(* Logix 5000 project; controller MyControlLogix vendor 1 type 14 code 51 rev 16.20; software revision 16.04; part 2 of 3 *)
(* tags used below, declared in another part *)
   AFC56 : AFC;
   AOI56AFC : AOI56AFC;
(* AOI56AFC, continued *)

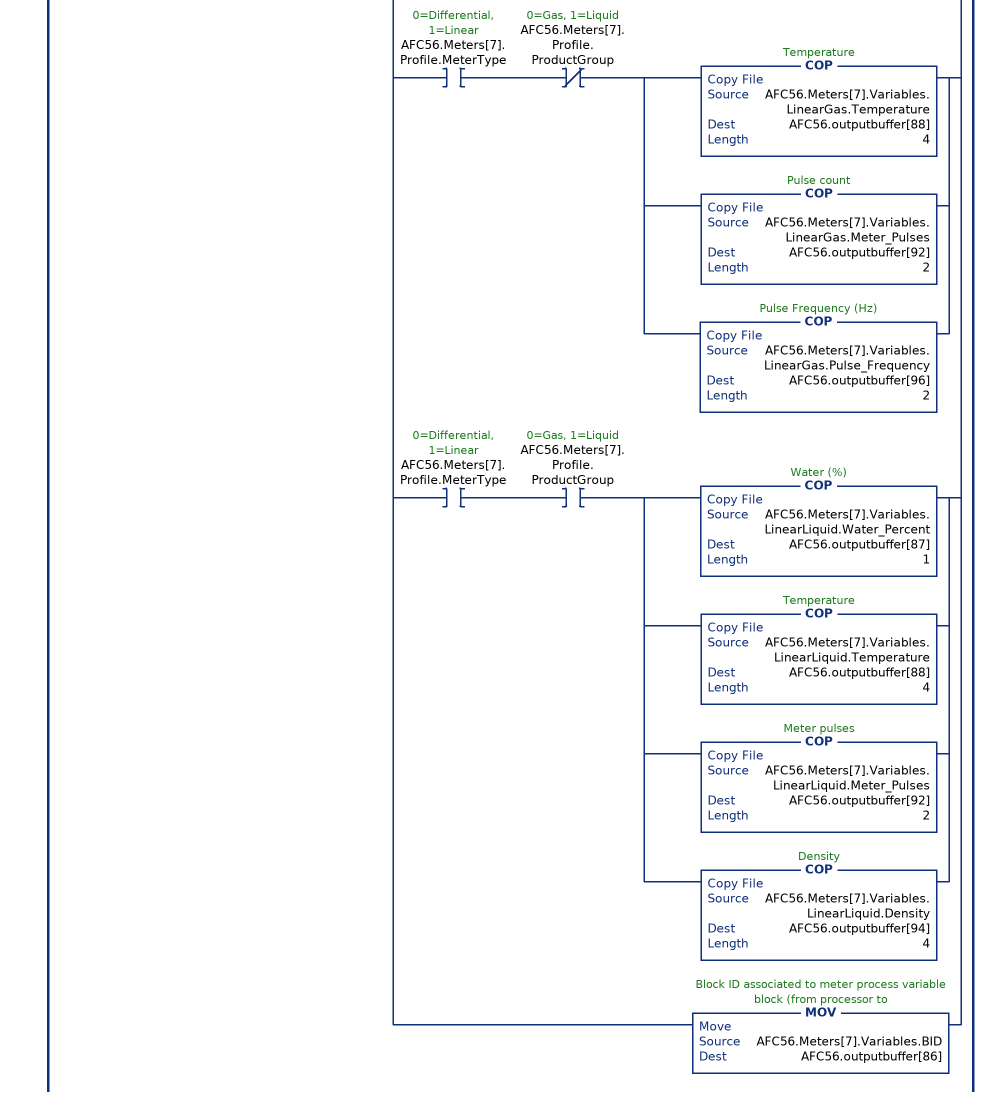
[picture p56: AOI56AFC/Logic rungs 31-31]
   31: XIO(AFC56.Flags.AFC_Set_Clock)LIM(1,AFC56.CycleCounter,16)[ADD(8,8192,AFC56.Meters[7].Variables.BID) ,XIO(AFC56.EnableStatus.Meter8) [OTE(AFC56.Meters[7].Variables.BID.8) ,OTU(AFC56.DisableMeter.Meter8) ] ,XIC(AFC56.EnableStatus.Meter8) OTU(AFC56.EnableMeter.Meter8) ,XIO(AFC56.Meters[7].Profile.MeterType) XIO(AFC56.Meters[7].Profile.ProductGroup) COP(AFC56.Meters[7].Variables.DifferentialGas.Temperature,AFC56.outputbuffer[88],6) ,XIO(AFC56.Meters[7].Profile.MeterType) XIC(AFC56.Meters[7].Profile.ProductGroup) [COP(AFC56.Meters[7].Variables.DifferentialLiquid.Water_Percent,AFC56.outputbuffer[87],1) ,COP(AFC56.Meters[7].Variables.DifferentialLiquid.Temperature,AFC56.outputbuffer[88],8) ] ,XIC(AFC56.Meters[7].Profile.MeterType) XIO(AFC56.Meters[7].Profile.ProductGroup) [COP(AFC56.Meters[7].Variables.LinearGas.Temperature,AFC56.outputbuffer[88],4) ,COP(AFC56.Meters[7].Variables.LinearGas.Meter_Pulses,AFC56.outputbuffer[92],2) ,COP(AFC56.Meters[7].Variables.LinearGas.Pulse_Frequency,AFC56.outputbuffer[96],2) ] ,XIC(AFC56.Meters[7].Profile.MeterType) XIC(AFC56.Meters[7].Profile.ProductGroup) [COP(AFC56.Meters[7].Variables.LinearLiquid.Water_Percent,AFC56.outputbuffer[87],1) ,COP(AFC56.Meters[7].Variables.LinearLiquid.Temperature,AFC56.outputbuffer[88],4) ,COP(AFC56.Meters[7].Variables.LinearLiquid.Meter_Pulses,AFC56.outputbuffer[92],2) ,COP(AFC56.Meters[7].Variables.LinearLiquid.Density,AFC56.outputbuffer[94],4) ] ,MOV(AFC56.Meters[7].Variables.BID,AFC56.outputbuffer[86]) ];
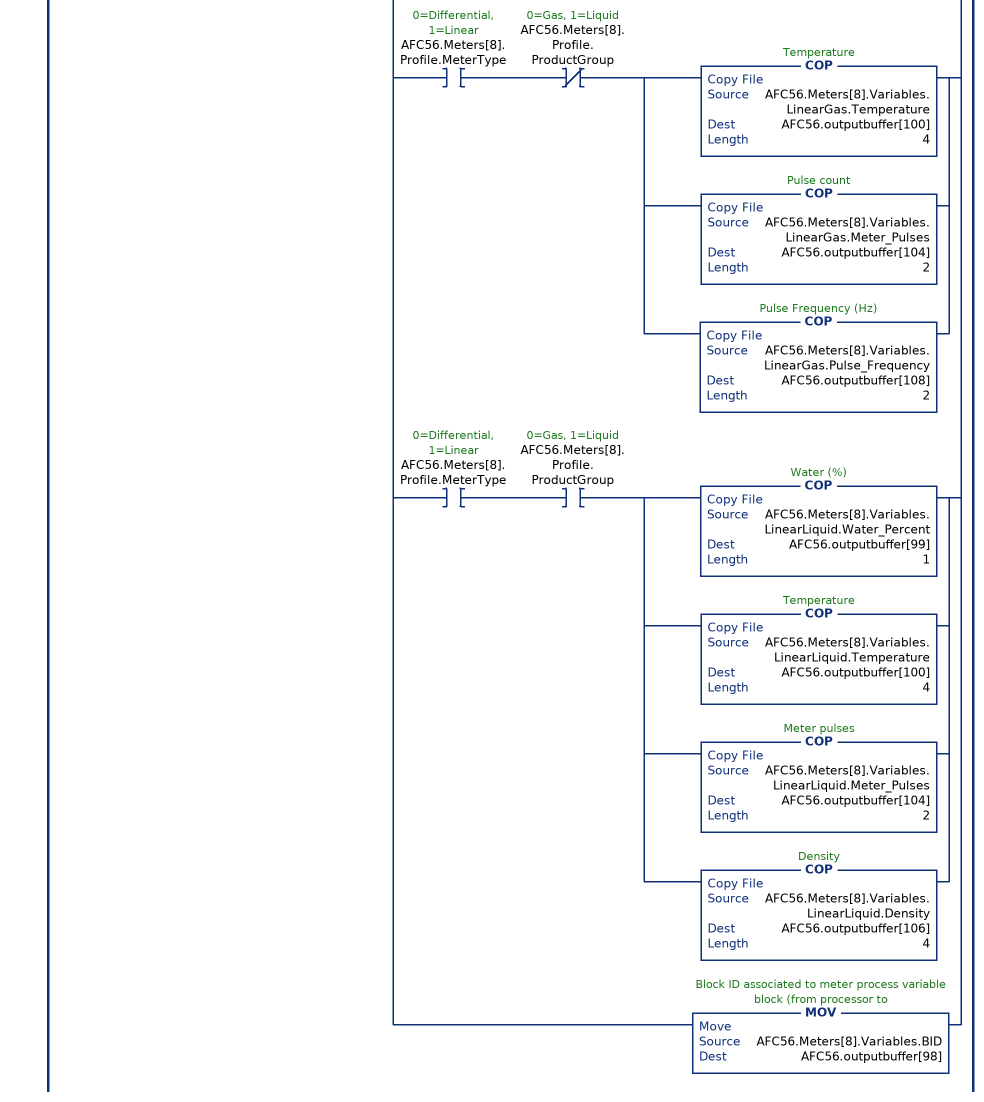
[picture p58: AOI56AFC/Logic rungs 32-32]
   32: XIO(AFC56.Flags.AFC_Set_Clock)LIM(1,AFC56.CycleCounter,16)[ADD(9,8192,AFC56.Meters[8].Variables.BID) ,XIO(AFC56.EnableStatus.Meter9) [OTE(AFC56.Meters[8].Variables.BID.8) ,OTU(AFC56.DisableMeter.Meter9) ] ,XIC(AFC56.EnableStatus.Meter9) OTU(AFC56.EnableMeter.Meter9) ,XIO(AFC56.Meters[8].Profile.MeterType) XIO(AFC56.Meters[8].Profile.ProductGroup) COP(AFC56.Meters[8].Variables.DifferentialGas.Temperature,AFC56.outputbuffer[100],6) ,XIO(AFC56.Meters[8].Profile.MeterType) XIC(AFC56.Meters[8].Profile.ProductGroup) [COP(AFC56.Meters[8].Variables.DifferentialLiquid.Water_Percent,AFC56.outputbuffer[99],1) ,COP(AFC56.Meters[8].Variables.DifferentialLiquid.Temperature,AFC56.outputbuffer[100],8) ] ,XIC(AFC56.Meters[8].Profile.MeterType) XIO(AFC56.Meters[8].Profile.ProductGroup) [COP(AFC56.Meters[8].Variables.LinearGas.Temperature,AFC56.outputbuffer[100],4) ,COP(AFC56.Meters[8].Variables.LinearGas.Meter_Pulses,AFC56.outputbuffer[104],2) ,COP(AFC56.Meters[8].Variables.LinearGas.Pulse_Frequency,AFC56.outputbuffer[108],2) ] ,XIC(AFC56.Meters[8].Profile.MeterType) XIC(AFC56.Meters[8].Profile.ProductGroup) [COP(AFC56.Meters[8].Variables.LinearLiquid.Water_Percent,AFC56.outputbuffer[99],1) ,COP(AFC56.Meters[8].Variables.LinearLiquid.Temperature,AFC56.outputbuffer[100],4) ,COP(AFC56.Meters[8].Variables.LinearLiquid.Meter_Pulses,AFC56.outputbuffer[104],2) ,COP(AFC56.Meters[8].Variables.LinearLiquid.Density,AFC56.outputbuffer[106],4) ] ,MOV(AFC56.Meters[8].Variables.BID,AFC56.outputbuffer[98]) ];
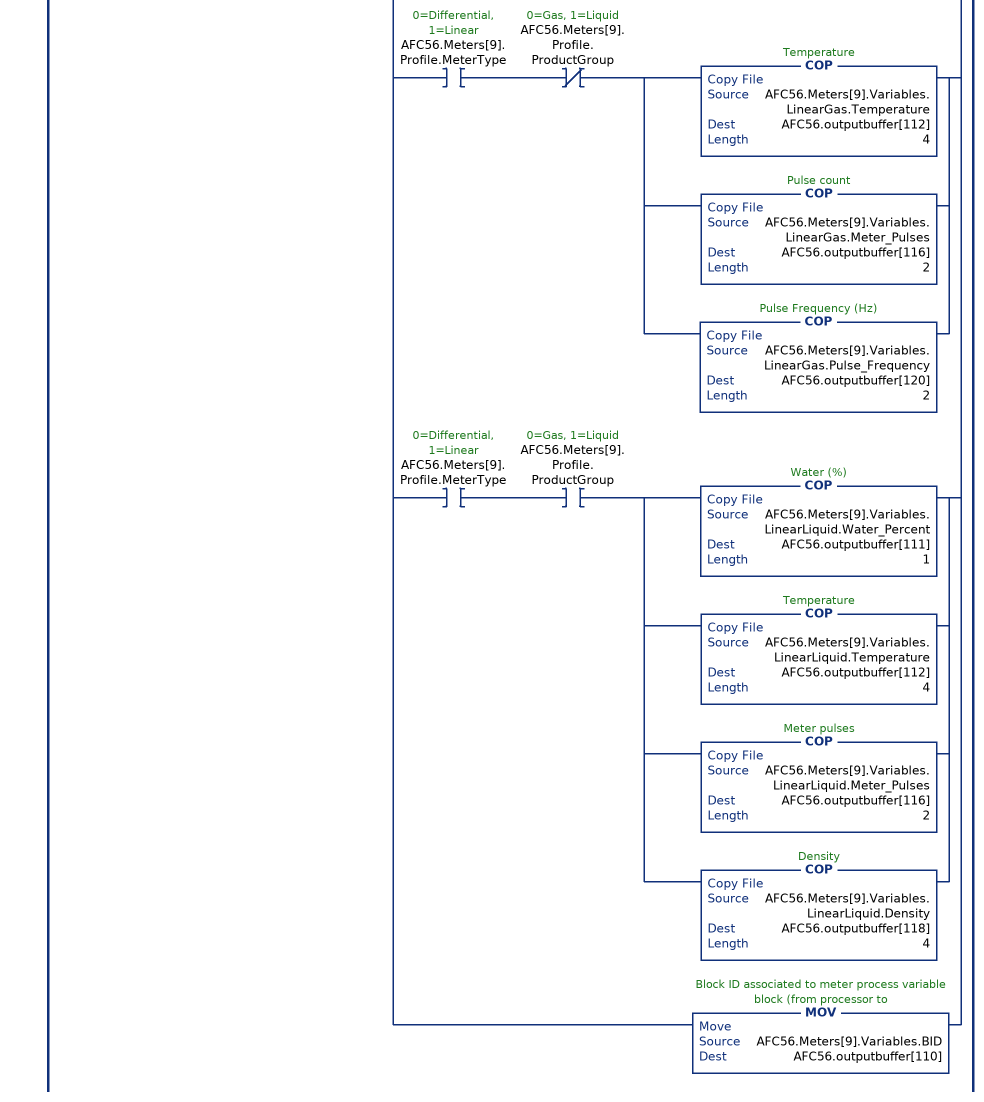
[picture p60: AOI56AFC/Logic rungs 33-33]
   33: XIO(AFC56.Flags.AFC_Set_Clock)LIM(1,AFC56.CycleCounter,16)[ADD(10,8192,AFC56.Meters[9].Variables.BID) ,XIO(AFC56.EnableStatus.Meter10) [OTE(AFC56.Meters[9].Variables.BID.8) ,OTU(AFC56.DisableMeter.Meter10) ] ,XIC(AFC56.EnableStatus.Meter10) OTU(AFC56.EnableMeter.Meter10) ,XIO(AFC56.Meters[9].Profile.MeterType) XIO(AFC56.Meters[9].Profile.ProductGroup) COP(AFC56.Meters[9].Variables.DifferentialGas.Temperature,AFC56.outputbuffer[112],6) ,XIO(AFC56.Meters[9].Profile.MeterType) XIC(AFC56.Meters[9].Profile.ProductGroup) [COP(AFC56.Meters[9].Variables.DifferentialLiquid.Water_Percent,AFC56.outputbuffer[111],1) ,COP(AFC56.Meters[9].Variables.DifferentialLiquid.Temperature,AFC56.outputbuffer[112],8) ] ,XIC(AFC56.Meters[9].Profile.MeterType) XIO(AFC56.Meters[9].Profile.ProductGroup) [COP(AFC56.Meters[9].Variables.LinearGas.Temperature,AFC56.outputbuffer[112],4) ,COP(AFC56.Meters[9].Variables.LinearGas.Meter_Pulses,AFC56.outputbuffer[116],2) ,COP(AFC56.Meters[9].Variables.LinearGas.Pulse_Frequency,AFC56.outputbuffer[120],2) ] ,XIC(AFC56.Meters[9].Profile.MeterType) XIC(AFC56.Meters[9].Profile.ProductGroup) [COP(AFC56.Meters[9].Variables.LinearLiquid.Water_Percent,AFC56.outputbuffer[111],1) ,COP(AFC56.Meters[9].Variables.LinearLiquid.Temperature,AFC56.outputbuffer[112],4) ,COP(AFC56.Meters[9].Variables.LinearLiquid.Meter_Pulses,AFC56.outputbuffer[116],2) ,COP(AFC56.Meters[9].Variables.LinearLiquid.Density,AFC56.outputbuffer[118],4) ] ,MOV(AFC56.Meters[9].Variables.BID,AFC56.outputbuffer[110]) ];
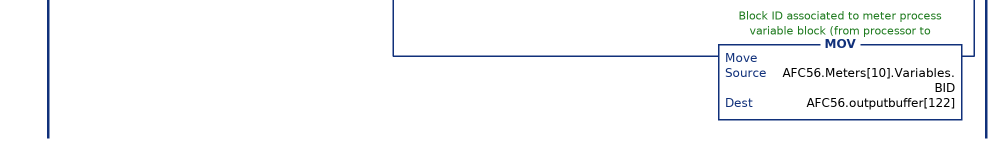
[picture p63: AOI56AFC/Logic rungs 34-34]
   34: XIO(AFC56.Flags.AFC_Set_Clock)LIM(1,AFC56.CycleCounter,16)[ADD(11,8192,AFC56.Meters[10].Variables.BID) ,XIO(AFC56.EnableStatus.Meter11) [OTE(AFC56.Meters[10].Variables.BID.8) ,OTU(AFC56.DisableMeter.Meter11) ] ,XIC(AFC56.EnableStatus.Meter11) OTU(AFC56.EnableMeter.Meter11) ,XIO(AFC56.Meters[10].Profile.MeterType) XIO(AFC56.Meters[10].Profile.ProductGroup) COP(AFC56.Meters[10].Variables.DifferentialGas.Temperature,AFC56.outputbuffer[124],6) ,XIO(AFC56.Meters[10].Profile.MeterType) XIC(AFC56.Meters[10].Profile.ProductGroup) [COP(AFC56.Meters[10].Variables.DifferentialLiquid.Water_Percent,AFC56.outputbuffer[123],1) ,COP(AFC56.Meters[10].Variables.DifferentialLiquid.Temperature,AFC56.outputbuffer[124],8) ] ,XIC(AFC56.Meters[10].Profile.MeterType) XIO(AFC56.Meters[10].Profile.ProductGroup) [COP(AFC56.Meters[10].Variables.LinearGas.Temperature,AFC56.outputbuffer[124],4) ,COP(AFC56.Meters[10].Variables.LinearGas.Meter_Pulses,AFC56.outputbuffer[128],2) ,COP(AFC56.Meters[10].Variables.LinearGas.Pulse_Frequency,AFC56.outputbuffer[132],2) ] ,XIC(AFC56.Meters[10].Profile.MeterType) XIC(AFC56.Meters[10].Profile.ProductGroup) [COP(AFC56.Meters[10].Variables.LinearLiquid.Water_Percent,AFC56.outputbuffer[123],1) ,COP(AFC56.Meters[10].Variables.LinearLiquid.Temperature,AFC56.outputbuffer[124],4) ,COP(AFC56.Meters[10].Variables.LinearLiquid.Meter_Pulses,AFC56.outputbuffer[128],2) ,COP(AFC56.Meters[10].Variables.LinearLiquid.Density,AFC56.outputbuffer[130],4) ] ,MOV(AFC56.Meters[10].Variables.BID,AFC56.outputbuffer[122]) ];
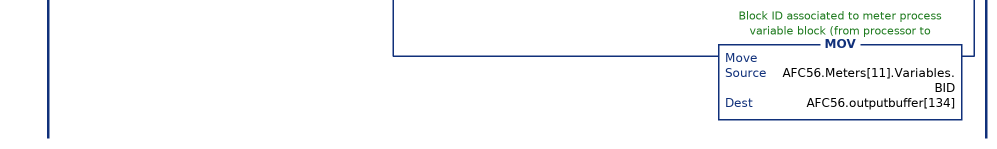
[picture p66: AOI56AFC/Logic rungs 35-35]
   35: XIO(AFC56.Flags.AFC_Set_Clock)LIM(1,AFC56.CycleCounter,16)[ADD(12,8192,AFC56.Meters[11].Variables.BID) ,XIO(AFC56.EnableStatus.Meter12) [OTE(AFC56.Meters[11].Variables.BID.8) ,OTU(AFC56.DisableMeter.Meter12) ] ,XIC(AFC56.EnableStatus.Meter12) OTU(AFC56.EnableMeter.Meter12) ,XIO(AFC56.Meters[11].Profile.MeterType) XIO(AFC56.Meters[11].Profile.ProductGroup) COP(AFC56.Meters[11].Variables.DifferentialGas.Temperature,AFC56.outputbuffer[136],6) ,XIO(AFC56.Meters[11].Profile.MeterType) XIC(AFC56.Meters[11].Profile.ProductGroup) [COP(AFC56.Meters[11].Variables.DifferentialLiquid.Water_Percent,AFC56.outputbuffer[135],1) ,COP(AFC56.Meters[11].Variables.DifferentialLiquid.Temperature,AFC56.outputbuffer[136],8) ] ,XIC(AFC56.Meters[11].Profile.MeterType) XIO(AFC56.Meters[11].Profile.ProductGroup) [COP(AFC56.Meters[11].Variables.LinearGas.Temperature,AFC56.outputbuffer[136],4) ,COP(AFC56.Meters[11].Variables.LinearGas.Meter_Pulses,AFC56.outputbuffer[140],2) ,COP(AFC56.Meters[11].Variables.LinearGas.Pulse_Frequency,AFC56.outputbuffer[144],2) ] ,XIC(AFC56.Meters[11].Profile.MeterType) XIC(AFC56.Meters[11].Profile.ProductGroup) [COP(AFC56.Meters[11].Variables.LinearLiquid.Water_Percent,AFC56.outputbuffer[135],1) ,COP(AFC56.Meters[11].Variables.LinearLiquid.Temperature,AFC56.outputbuffer[136],4) ,COP(AFC56.Meters[11].Variables.LinearLiquid.Meter_Pulses,AFC56.outputbuffer[140],2) ,COP(AFC56.Meters[11].Variables.LinearLiquid.Density,AFC56.outputbuffer[142],4) ] ,MOV(AFC56.Meters[11].Variables.BID,AFC56.outputbuffer[134]) ];
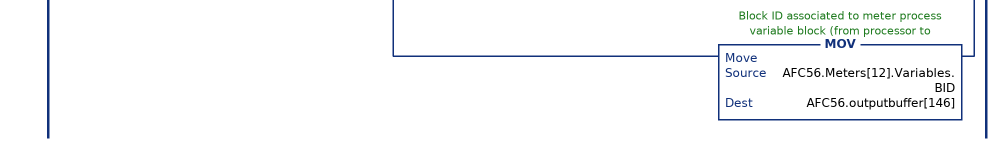
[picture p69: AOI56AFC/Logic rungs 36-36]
   36: XIO(AFC56.Flags.AFC_Set_Clock)LIM(1,AFC56.CycleCounter,16)[ADD(13,8192,AFC56.Meters[12].Variables.BID) ,XIO(AFC56.EnableStatus.Meter13) [OTE(AFC56.Meters[12].Variables.BID.8) ,OTU(AFC56.DisableMeter.Meter13) ] ,XIC(AFC56.EnableStatus.Meter13) OTU(AFC56.EnableMeter.Meter13) ,XIO(AFC56.Meters[12].Profile.MeterType) XIO(AFC56.Meters[12].Profile.ProductGroup) COP(AFC56.Meters[12].Variables.DifferentialGas.Temperature,AFC56.outputbuffer[148],6) ,XIO(AFC56.Meters[12].Profile.MeterType) XIC(AFC56.Meters[12].Profile.ProductGroup) [COP(AFC56.Meters[12].Variables.DifferentialLiquid.Water_Percent,AFC56.outputbuffer[147],1) ,COP(AFC56.Meters[12].Variables.DifferentialLiquid.Temperature,AFC56.outputbuffer[148],8) ] ,XIC(AFC56.Meters[12].Profile.MeterType) XIO(AFC56.Meters[12].Profile.ProductGroup) [COP(AFC56.Meters[12].Variables.LinearGas.Temperature,AFC56.outputbuffer[148],4) ,COP(AFC56.Meters[12].Variables.LinearGas.Meter_Pulses,AFC56.outputbuffer[152],2) ,COP(AFC56.Meters[12].Variables.LinearGas.Pulse_Frequency,AFC56.outputbuffer[156],2) ] ,XIC(AFC56.Meters[12].Profile.MeterType) XIC(AFC56.Meters[12].Profile.ProductGroup) [COP(AFC56.Meters[12].Variables.LinearLiquid.Water_Percent,AFC56.outputbuffer[147],1) ,COP(AFC56.Meters[12].Variables.LinearLiquid.Temperature,AFC56.outputbuffer[148],4) ,COP(AFC56.Meters[12].Variables.LinearLiquid.Meter_Pulses,AFC56.outputbuffer[152],2) ,COP(AFC56.Meters[12].Variables.LinearLiquid.Density,AFC56.outputbuffer[154],4) ] ,MOV(AFC56.Meters[12].Variables.BID,AFC56.outputbuffer[146]) ];
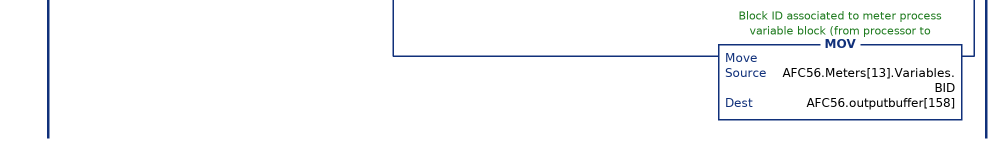
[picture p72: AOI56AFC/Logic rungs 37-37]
   37: XIO(AFC56.Flags.AFC_Set_Clock)LIM(1,AFC56.CycleCounter,16)[ADD(14,8192,AFC56.Meters[13].Variables.BID) ,XIO(AFC56.EnableStatus.Meter14) [OTE(AFC56.Meters[13].Variables.BID.8) ,OTU(AFC56.DisableMeter.Meter14) ] ,XIC(AFC56.EnableStatus.Meter14) OTU(AFC56.EnableMeter.Meter14) ,XIO(AFC56.Meters[13].Profile.MeterType) XIO(AFC56.Meters[13].Profile.ProductGroup) COP(AFC56.Meters[13].Variables.DifferentialGas.Temperature,AFC56.outputbuffer[160],6) ,XIO(AFC56.Meters[13].Profile.MeterType) XIC(AFC56.Meters[13].Profile.ProductGroup) [COP(AFC56.Meters[13].Variables.DifferentialLiquid.Water_Percent,AFC56.outputbuffer[159],1) ,COP(AFC56.Meters[13].Variables.DifferentialLiquid.Temperature,AFC56.outputbuffer[160],8) ] ,XIC(AFC56.Meters[13].Profile.MeterType) XIO(AFC56.Meters[13].Profile.ProductGroup) [COP(AFC56.Meters[13].Variables.LinearGas.Temperature,AFC56.outputbuffer[160],4) ,COP(AFC56.Meters[13].Variables.LinearGas.Meter_Pulses,AFC56.outputbuffer[164],2) ,COP(AFC56.Meters[13].Variables.LinearGas.Pulse_Frequency,AFC56.outputbuffer[168],2) ] ,XIC(AFC56.Meters[13].Profile.MeterType) XIC(AFC56.Meters[13].Profile.ProductGroup) [COP(AFC56.Meters[13].Variables.LinearLiquid.Water_Percent,AFC56.outputbuffer[159],1) ,COP(AFC56.Meters[13].Variables.LinearLiquid.Temperature,AFC56.outputbuffer[160],4) ,COP(AFC56.Meters[13].Variables.LinearLiquid.Meter_Pulses,AFC56.outputbuffer[164],2) ,COP(AFC56.Meters[13].Variables.LinearLiquid.Density,AFC56.outputbuffer[166],4) ] ,MOV(AFC56.Meters[13].Variables.BID,AFC56.outputbuffer[158]) ];
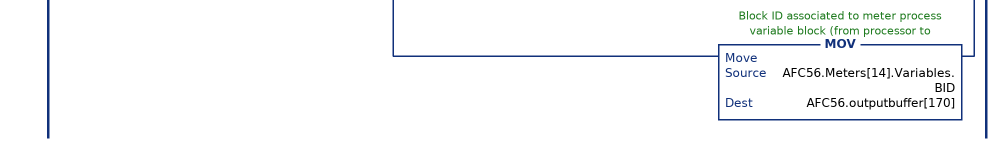
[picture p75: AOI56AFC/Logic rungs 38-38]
   38: XIO(AFC56.Flags.AFC_Set_Clock)LIM(1,AFC56.CycleCounter,16)[ADD(15,8192,AFC56.Meters[14].Variables.BID) ,XIO(AFC56.EnableStatus.Meter15) [OTE(AFC56.Meters[14].Variables.BID.8) ,OTU(AFC56.DisableMeter.Meter15) ] ,XIC(AFC56.EnableStatus.Meter15) OTU(AFC56.EnableMeter.Meter15) ,XIO(AFC56.Meters[14].Profile.MeterType) XIO(AFC56.Meters[14].Profile.ProductGroup) COP(AFC56.Meters[14].Variables.DifferentialGas.Temperature,AFC56.outputbuffer[172],6) ,XIO(AFC56.Meters[14].Profile.MeterType) XIC(AFC56.Meters[14].Profile.ProductGroup) [COP(AFC56.Meters[14].Variables.DifferentialLiquid.Water_Percent,AFC56.outputbuffer[171],1) ,COP(AFC56.Meters[14].Variables.DifferentialLiquid.Temperature,AFC56.outputbuffer[172],8) ] ,XIC(AFC56.Meters[14].Profile.MeterType) XIO(AFC56.Meters[14].Profile.ProductGroup) [COP(AFC56.Meters[14].Variables.LinearGas.Temperature,AFC56.outputbuffer[172],4) ,COP(AFC56.Meters[14].Variables.LinearGas.Meter_Pulses,AFC56.outputbuffer[176],2) ,COP(AFC56.Meters[14].Variables.LinearGas.Pulse_Frequency,AFC56.outputbuffer[180],2) ] ,XIC(AFC56.Meters[14].Profile.MeterType) XIC(AFC56.Meters[14].Profile.ProductGroup) [COP(AFC56.Meters[14].Variables.LinearLiquid.Water_Percent,AFC56.outputbuffer[171],1) ,COP(AFC56.Meters[14].Variables.LinearLiquid.Temperature,AFC56.outputbuffer[172],4) ,COP(AFC56.Meters[14].Variables.LinearLiquid.Meter_Pulses,AFC56.outputbuffer[176],2) ,COP(AFC56.Meters[14].Variables.LinearLiquid.Density,AFC56.outputbuffer[178],4) ] ,MOV(AFC56.Meters[14].Variables.BID,AFC56.outputbuffer[170]) ];
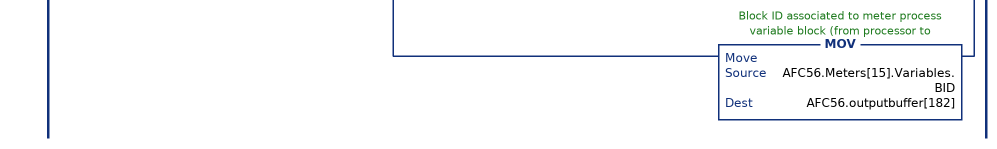
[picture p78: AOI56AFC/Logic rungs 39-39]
   39: XIO(AFC56.Flags.AFC_Set_Clock)LIM(1,AFC56.CycleCounter,16)[ADD(16,8192,AFC56.Meters[15].Variables.BID) ,XIO(AFC56.EnableStatus.Meter16) [OTE(AFC56.Meters[15].Variables.BID.8) ,OTU(AFC56.DisableMeter.Meter16) ] ,XIC(AFC56.EnableStatus.Meter16) OTU(AFC56.EnableMeter.Meter16) ,XIO(AFC56.Meters[15].Profile.MeterType) XIO(AFC56.Meters[15].Profile.ProductGroup) COP(AFC56.Meters[15].Variables.DifferentialGas.Temperature,AFC56.outputbuffer[184],6) ,XIO(AFC56.Meters[15].Profile.MeterType) XIC(AFC56.Meters[15].Profile.ProductGroup) [COP(AFC56.Meters[15].Variables.DifferentialLiquid.Water_Percent,AFC56.outputbuffer[183],1) ,COP(AFC56.Meters[15].Variables.DifferentialLiquid.Temperature,AFC56.outputbuffer[184],8) ] ,XIC(AFC56.Meters[15].Profile.MeterType) XIO(AFC56.Meters[15].Profile.ProductGroup) [COP(AFC56.Meters[15].Variables.LinearGas.Temperature,AFC56.outputbuffer[184],4) ,COP(AFC56.Meters[15].Variables.LinearGas.Meter_Pulses,AFC56.outputbuffer[188],2) ,COP(AFC56.Meters[15].Variables.LinearGas.Pulse_Frequency,AFC56.outputbuffer[192],2) ] ,XIC(AFC56.Meters[15].Profile.MeterType) XIC(AFC56.Meters[15].Profile.ProductGroup) [COP(AFC56.Meters[15].Variables.LinearLiquid.Water_Percent,AFC56.outputbuffer[183],1) ,COP(AFC56.Meters[15].Variables.LinearLiquid.Temperature,AFC56.outputbuffer[184],4) ,COP(AFC56.Meters[15].Variables.LinearLiquid.Meter_Pulses,AFC56.outputbuffer[188],2) ,COP(AFC56.Meters[15].Variables.LinearLiquid.Density,AFC56.outputbuffer[190],4) ] ,MOV(AFC56.Meters[15].Variables.BID,AFC56.outputbuffer[182]) ];
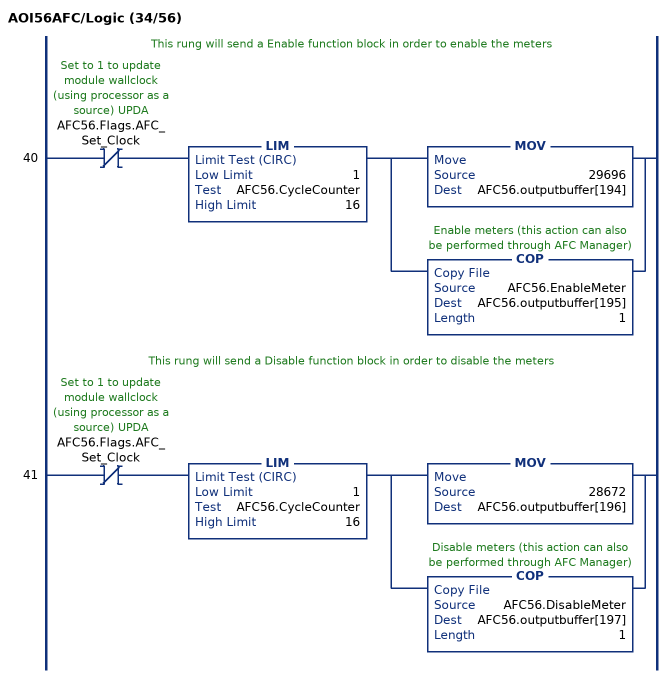
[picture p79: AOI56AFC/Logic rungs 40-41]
   // This rung will send a Enable function block in order to enable the meters
   40: XIO(AFC56.Flags.AFC_Set_Clock)LIM(1,AFC56.CycleCounter,16)[MOV(29696,AFC56.outputbuffer[194]) ,COP(AFC56.EnableMeter,AFC56.outputbuffer[195],1) ];
   // This rung will send a Disable function block in order to disable the meters
   41: XIO(AFC56.Flags.AFC_Set_Clock)LIM(1,AFC56.CycleCounter,16)[MOV(28672,AFC56.outputbuffer[196]) ,COP(AFC56.DisableMeter,AFC56.outputbuffer[197],1) ];
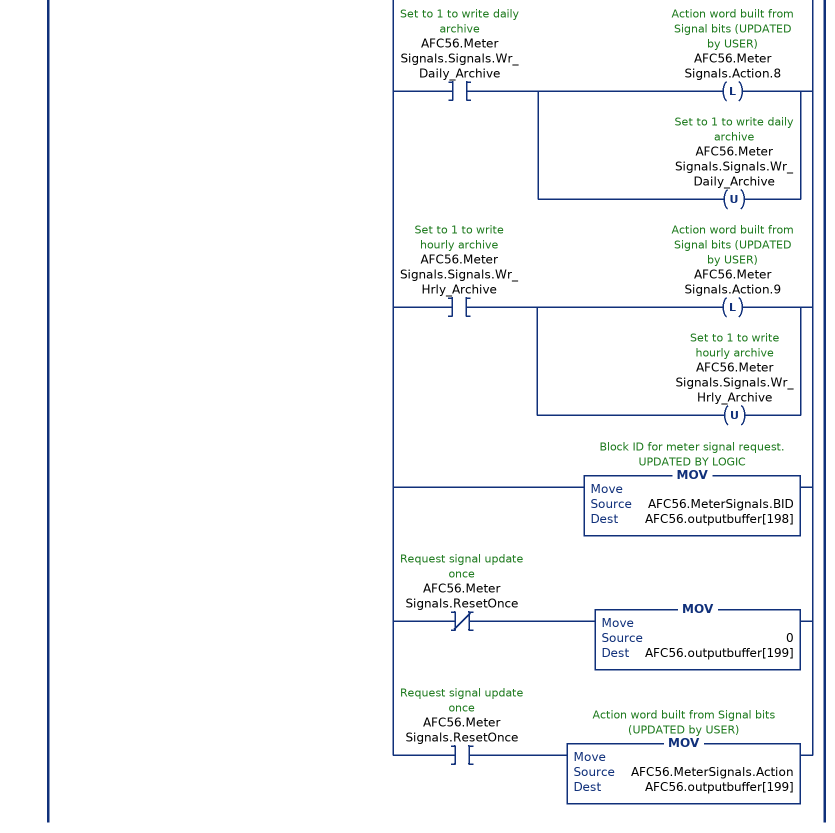
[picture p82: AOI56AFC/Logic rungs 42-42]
   // This rung will allow the ladder logic to reset any accumulator or to write a daily or hourly archive
   42: XIO(AFC56.Flags.AFC_Set_Clock)LIM(1,AFC56.CycleCounter,16)[ADD(12288,AFC56.MeterSignals.Meter,AFC56.MeterSignals.BID) ,XIO(AFC56.MeterSignals.Enable) OTE(AFC56.MeterSignals.BID.8) ,XIC(AFC56.MeterSignals.Signals.Sel_Stream1) [OTL(AFC56.MeterSignals.Action.0) ,OTU(AFC56.MeterSignals.Signals.Sel_Stream1) ] ,XIC(AFC56.MeterSignals.Signals.Sel_Stream2) [OTL(AFC56.MeterSignals.Action.1) ,OTU(AFC56.MeterSignals.Signals.Sel_Stream2) ] ,XIC(AFC56.MeterSignals.Signals.Sel_Stream3) [OTL(AFC56.MeterSignals.Action.2) ,OTU(AFC56.MeterSignals.Signals.Sel_Stream3) ] ,XIC(AFC56.MeterSignals.Signals.Sel_Stream4) [OTL(AFC56.MeterSignals.Action.3) ,OTU(AFC56.MeterSignals.Signals.Sel_Stream4) ] ,XIC(AFC56.MeterSignals.Signals.Res_Acc1) [OTL(AFC56.MeterSignals.Action.4) ,OTU(AFC56.MeterSignals.Signals.Res_Acc1) ] ,XIC(AFC56.MeterSignals.Signals.Res_Acc2) [OTL(AFC56.MeterSignals.Action.5) ,OTU(AFC56.MeterSignals.Signals.Res_Acc2) ] ,XIC(AFC56.MeterSignals.Signals.Res_Acc3) [OTL(AFC56.MeterSignals.Action.6) ,OTU(AFC56.MeterSignals.Signals.Res_Acc3) ] ,XIC(AFC56.MeterSignals.Signals.Res_Acc4) [OTL(AFC56.MeterSignals.Action.7) ,OTU(AFC56.MeterSignals.Signals.Res_Acc4) ] ,XIC(AFC56.MeterSignals.Signals.Wr_Daily_Archive) [OTL(AFC56.MeterSignals.Action.8) ,OTU(AFC56.MeterSignals.Signals.Wr_Daily_Archive) ] ,XIC(AFC56.MeterSignals.Signals.Wr_Hrly_Archive) [OTL(AFC56.MeterSignals.Action.9) ,OTU(AFC56.MeterSignals.Signals.Wr_Hrly_Archive) ] ,MOV(AFC56.MeterSignals.BID,AFC56.outputbuffer[198]) ,XIO(AFC56.MeterSignals.ResetOnce) MOV(0,AFC56.outputbuffer[199]) ,XIC(AFC56.MeterSignals.ResetOnce) MOV(AFC56.MeterSignals.Action,AFC56.outputbuffer[199]) ];
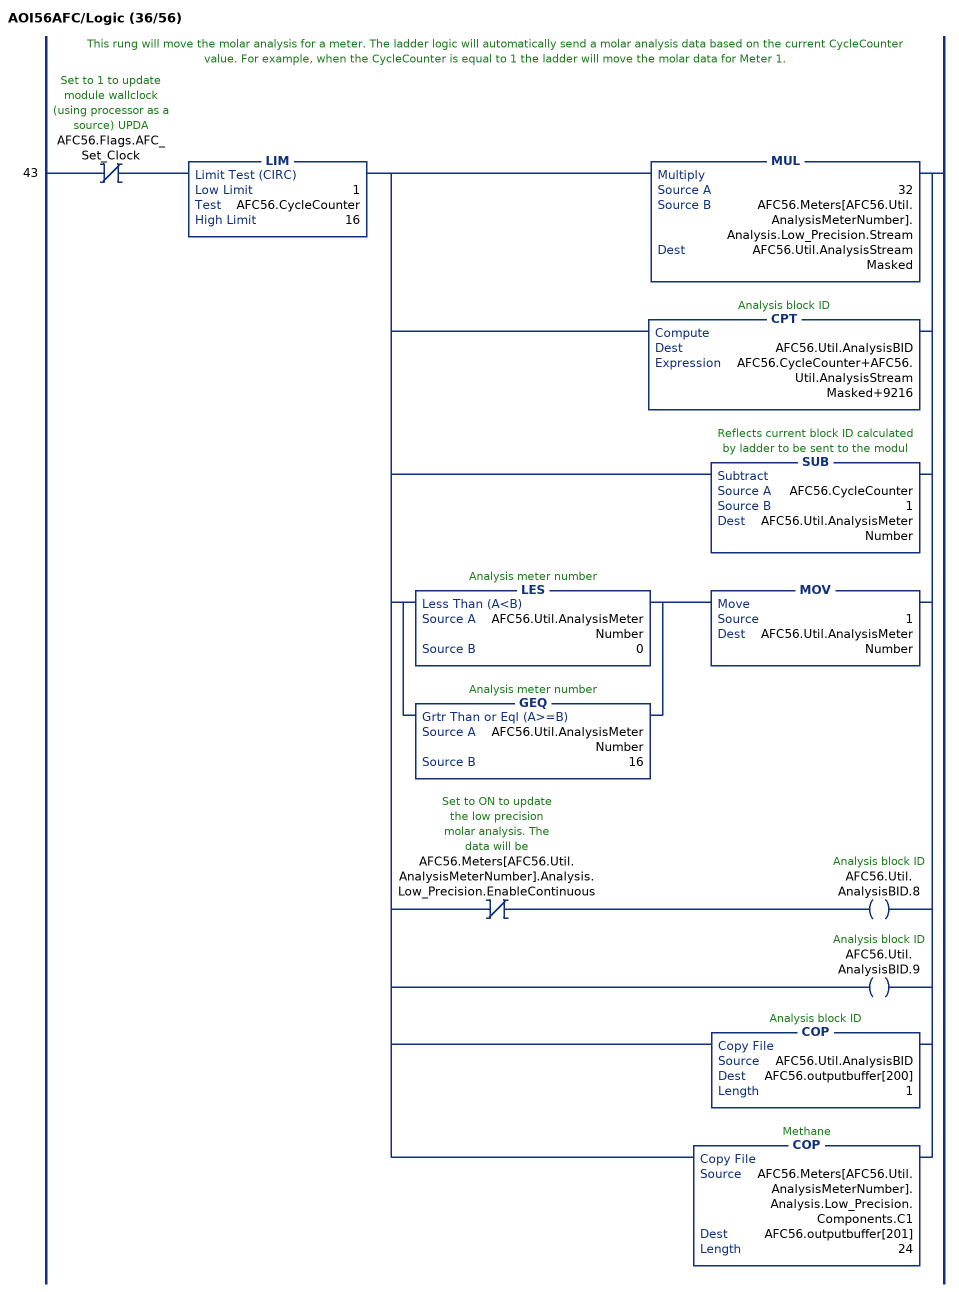
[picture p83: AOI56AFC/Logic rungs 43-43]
   // This rung will move the molar analysis for a meter. The ladder logic will automatically send a molar analysis data based on the current CycleCounter value. For example, when the CycleCounter is equal to 1 the ladder will move the molar data for Meter 1.
   43: XIO(AFC56.Flags.AFC_Set_Clock)LIM(1,AFC56.CycleCounter,16)[MUL(32,AFC56.Meters[AFC56.Util.AnalysisMeterNumber].Analysis.Low_Precision.Stream,AFC56.Util.AnalysisStreamMasked) ,CPT(AFC56.Util.AnalysisBID,AFC56.CycleCounter+AFC56.Util.AnalysisStreamMasked+9216) ,SUB(AFC56.CycleCounter,1,AFC56.Util.AnalysisMeterNumber) ,[LES(AFC56.Util.AnalysisMeterNumber,0) ,GEQ(AFC56.Util.AnalysisMeterNumber,16) ] MOV(1,AFC56.Util.AnalysisMeterNumber) ,XIO(AFC56.Meters[AFC56.Util.AnalysisMeterNumber].Analysis.Low_Precision.EnableContinuous) OTE(AFC56.Util.AnalysisBID.8) ,OTE(AFC56.Util.AnalysisBID.9) ,COP(AFC56.Util.AnalysisBID,AFC56.outputbuffer[200],1) ,COP(AFC56.Meters[AFC56.Util.AnalysisMeterNumber].Analysis.Low_Precision.Components.C1,AFC56.outputbuffer[201],24) ];
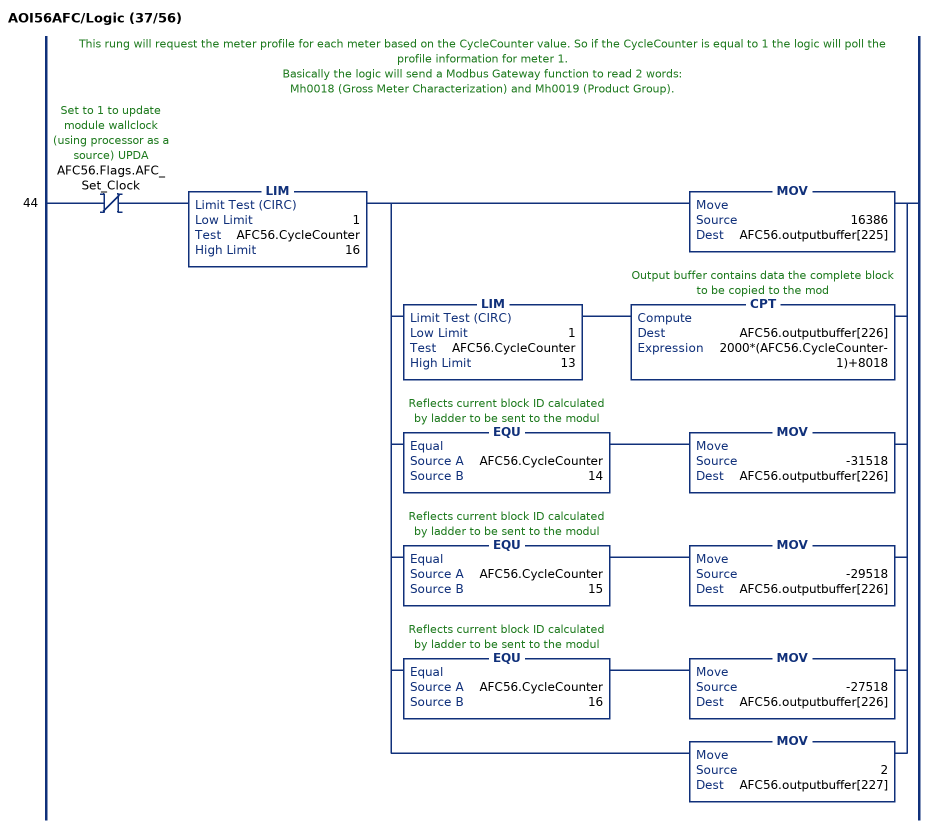
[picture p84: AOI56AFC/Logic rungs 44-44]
   // This rung will request the meter profile for each meter based on the CycleCounter value. So if the CycleCounter is equal to 1 the logic will poll the profile information for meter 1.
   // Basically the logic will send a Modbus Gateway function to read 2 words:
   // Mh0018 (Gross Meter Characterization) and Mh0019 (Product Group).
   44: XIO(AFC56.Flags.AFC_Set_Clock)LIM(1,AFC56.CycleCounter,16)[MOV(16386,AFC56.outputbuffer[225]) ,LIM(1,AFC56.CycleCounter,13) CPT(AFC56.outputbuffer[226],2000*(AFC56.CycleCounter-1)+8018) ,EQU(AFC56.CycleCounter,14) MOV(-31518,AFC56.outputbuffer[226]) ,EQU(AFC56.CycleCounter,15) MOV(-29518,AFC56.outputbuffer[226]) ,EQU(AFC56.CycleCounter,16) MOV(-27518,AFC56.outputbuffer[226]) ,MOV(2,AFC56.outputbuffer[227]) ];
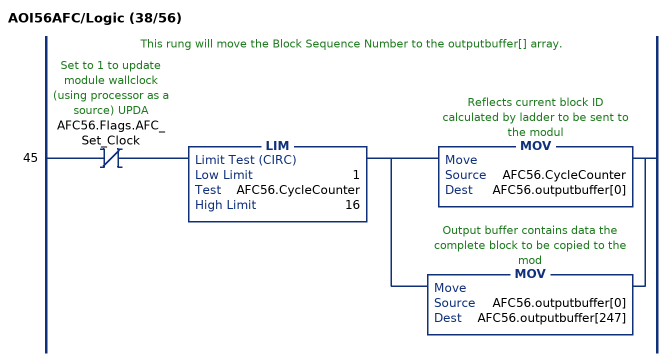
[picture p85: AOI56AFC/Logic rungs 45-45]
   // This rung will move the Block Sequence Number to the outputbuffer[] array.
   45: XIO(AFC56.Flags.AFC_Set_Clock)LIM(1,AFC56.CycleCounter,16)[MOV(AFC56.CycleCounter,AFC56.outputbuffer[0]) ,MOV(AFC56.outputbuffer[0],AFC56.outputbuffer[247]) ];
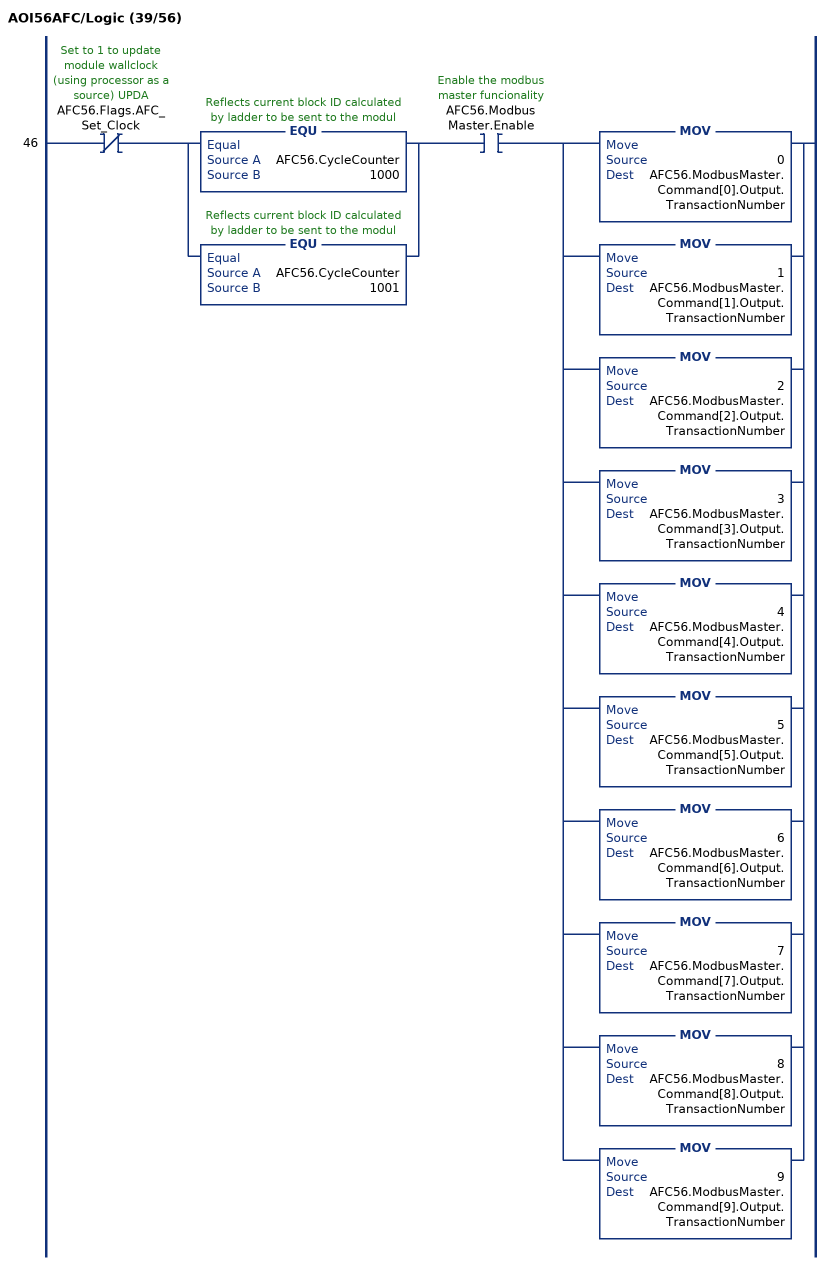
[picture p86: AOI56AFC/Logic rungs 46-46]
   46: XIO(AFC56.Flags.AFC_Set_Clock)[EQU(AFC56.CycleCounter,1000) ,EQU(AFC56.CycleCounter,1001) ]XIC(AFC56.ModbusMaster.Enable)[MOV(0,AFC56.ModbusMaster.Command[0].Output.TransactionNumber) ,MOV(1,AFC56.ModbusMaster.Command[1].Output.TransactionNumber) ,MOV(2,AFC56.ModbusMaster.Command[2].Output.TransactionNumber) ,MOV(3,AFC56.ModbusMaster.Command[3].Output.TransactionNumber) ,MOV(4,AFC56.ModbusMaster.Command[4].Output.TransactionNumber) ,MOV(5,AFC56.ModbusMaster.Command[5].Output.TransactionNumber) ,MOV(6,AFC56.ModbusMaster.Command[6].Output.TransactionNumber) ,MOV(7,AFC56.ModbusMaster.Command[7].Output.TransactionNumber) ,MOV(8,AFC56.ModbusMaster.Command[8].Output.TransactionNumber) ,MOV(9,AFC56.ModbusMaster.Command[9].Output.TransactionNumber) ];
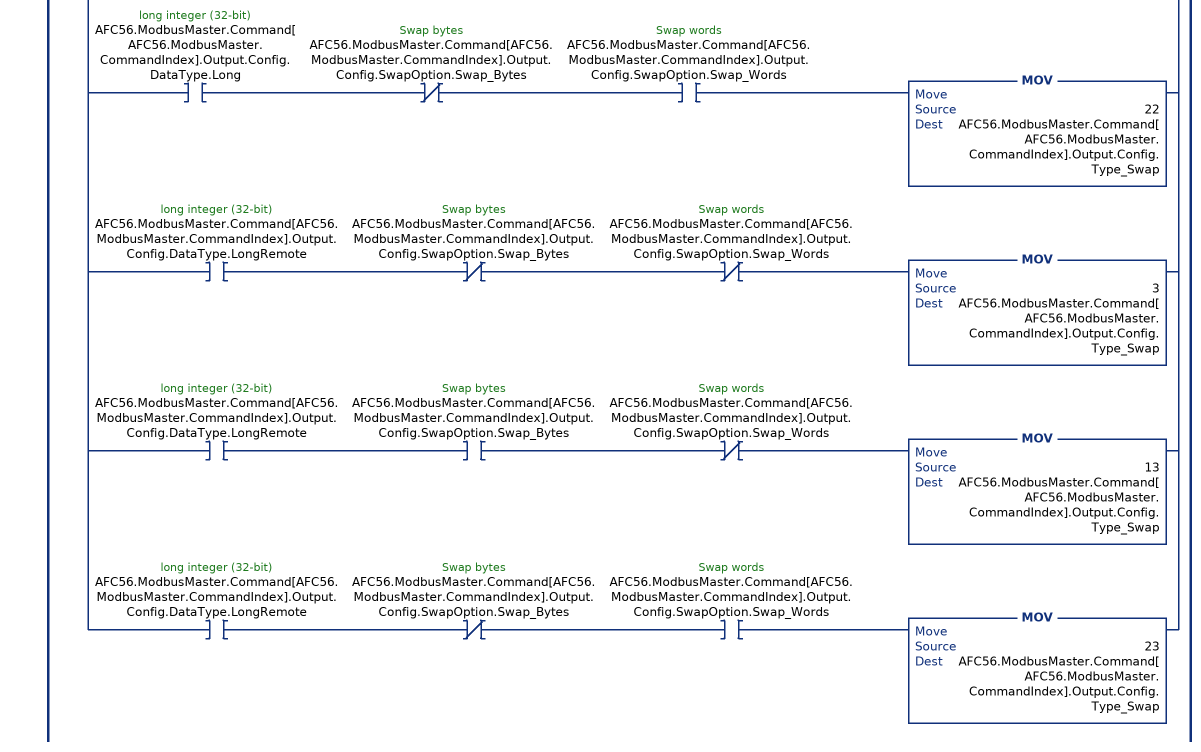
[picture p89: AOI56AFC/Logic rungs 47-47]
   // This handles the Modbus Master logic
   47: XIO(AFC56.Flags.AFC_Set_Clock)[EQU(AFC56.CycleCounter,1000) ,EQU(AFC56.CycleCounter,1001) ]XIC(AFC56.ModbusMaster.Enable)[[MOV(24576,AFC56.ModbusMaster.Command[AFC56.ModbusMaster.CommandIndex].Output.BOD) ,ADD(AFC56.ModbusMaster.Command[AFC56.ModbusMaster.CommandIndex].Output.BOD,130,AFC56.ModbusMaster.Command[AFC56.ModbusMaster.CommandIndex].Output.BOD) ] ,XIC(AFC56.ModbusMaster.Command[AFC56.ModbusMaster.CommandIndex].Output.Config.FunctionType_Write) OTE(AFC56.ModbusMaster.Command[AFC56.ModbusMaster.CommandIndex].Output.BOD.11) ,XIO(AFC56.ModbusMaster.Command[AFC56.ModbusMaster.CommandIndex].Output.Config.Enable) OTE(AFC56.ModbusMaster.Command[AFC56.ModbusMaster.CommandIndex].Output.BOD.8) ,XIC(AFC56.ModbusMaster.Command[AFC56.ModbusMaster.CommandIndex].Output.Config.RegisterBank_Input) OTE(AFC56.ModbusMaster.Command[AFC56.ModbusMaster.CommandIndex].Output.BOD.10) ,XIC(AFC56.ModbusMaster.Command[AFC56.ModbusMaster.CommandIndex].Output.Config.DataType.Bit) MOV(0,AFC56.ModbusMaster.Command[AFC56.ModbusMaster.CommandIndex].Output.Config.Type_Swap) ,XIC(AFC56.ModbusMaster.Command[AFC56.ModbusMaster.CommandIndex].Output.Config.DataType.Word) XIO(AFC56.ModbusMaster.Command[AFC56.ModbusMaster.CommandIndex].Output.Config.SwapOption.Swap_Bytes) MOV(1,AFC56.ModbusMaster.Command[AFC56.ModbusMaster.CommandIndex].Output.Config.Type_Swap) ,XIC(AFC56.ModbusMaster.Command[AFC56.ModbusMaster.CommandIndex].Output.Config.DataType.Word) XIC(AFC56.ModbusMaster.Command[AFC56.ModbusMaster.CommandIndex].Output.Config.SwapOption.Swap_Bytes) MOV(11,AFC56.ModbusMaster.Command[AFC56.ModbusMaster.CommandIndex].Output.Config.Type_Swap) ,XIC(AFC56.ModbusMaster.Command[AFC56.ModbusMaster.CommandIndex].Output.Config.DataType.Long) XIO(AFC56.ModbusMaster.Command[AFC56.ModbusMaster.CommandIndex].Output.Config.SwapOption.Swap_Bytes) XIO(AFC56.ModbusMaster.Command[AFC56.ModbusMaster.CommandIndex].Output.Config.SwapOption.Swap_Words) MOV(2,AFC56.ModbusMaster.Command[AFC56.ModbusMaster.CommandIndex].Output.Config.Type_Swap) ,XIC(AFC56.ModbusMaster.Command[AFC56.ModbusMaster.CommandIndex].Output.Config.DataType.Long) XIC(AFC56.ModbusMaster.Command[AFC56.ModbusMaster.CommandIndex].Output.Config.SwapOption.Swap_Bytes) XIO(AFC56.ModbusMaster.Command[AFC56.ModbusMaster.CommandIndex].Output.Config.SwapOption.Swap_Words) MOV(12,AFC56.ModbusMaster.Command[AFC56.ModbusMaster.CommandIndex].Output.Config.Type_Swap) ,XIC(AFC56.ModbusMaster.Command[AFC56.ModbusMaster.CommandIndex].Output.Config.DataType.Long) XIO(AFC56.ModbusMaster.Command[AFC56.ModbusMaster.CommandIndex].Output.Config.SwapOption.Swap_Bytes) XIC(AFC56.ModbusMaster.Command[AFC56.ModbusMaster.CommandIndex].Output.Config.SwapOption.Swap_Words) MOV(22,AFC56.ModbusMaster.Command[AFC56.ModbusMaster.CommandIndex].Output.Config.Type_Swap) ,XIC(AFC56.ModbusMaster.Command[AFC56.ModbusMaster.CommandIndex].Output.Config.DataType.LongRemote) XIO(AFC56.ModbusMaster.Command[AFC56.ModbusMaster.CommandIndex].Output.Config.SwapOption.Swap_Bytes) XIO(AFC56.ModbusMaster.Command[AFC56.ModbusMaster.CommandIndex].Output.Config.SwapOption.Swap_Words) MOV(3,AFC56.ModbusMaster.Command[AFC56.ModbusMaster.CommandIndex].Output.Config.Type_Swap) ,XIC(AFC56.ModbusMaster.Command[AFC56.ModbusMaster.CommandIndex].Output.Config.DataType.LongRemote) XIC(AFC56.ModbusMaster.Command[AFC56.ModbusMaster.CommandIndex].Output.Config.SwapOption.Swap_Bytes) XIO(AFC56.ModbusMaster.Command[AFC56.ModbusMaster.CommandIndex].Output.Config.SwapOption.Swap_Words) MOV(13,AFC56.ModbusMaster.Command[AFC56.ModbusMaster.CommandIndex].Output.Config.Type_Swap) ,XIC(AFC56.ModbusMaster.Command[AFC56.ModbusMaster.CommandIndex].Output.Config.DataType.LongRemote) XIO(AFC56.ModbusMaster.Command[AFC56.ModbusMaster.CommandIndex].Output.Config.SwapOption.Swap_Bytes) XIC(AFC56.ModbusMaster.Command[AFC56.ModbusMaster.CommandIndex].Output.Config.SwapOption.Swap_Words) MOV(23,AFC56.ModbusMaster.Command[AFC56.ModbusMaster.CommandIndex].Output.Config.Type_Swap) ];
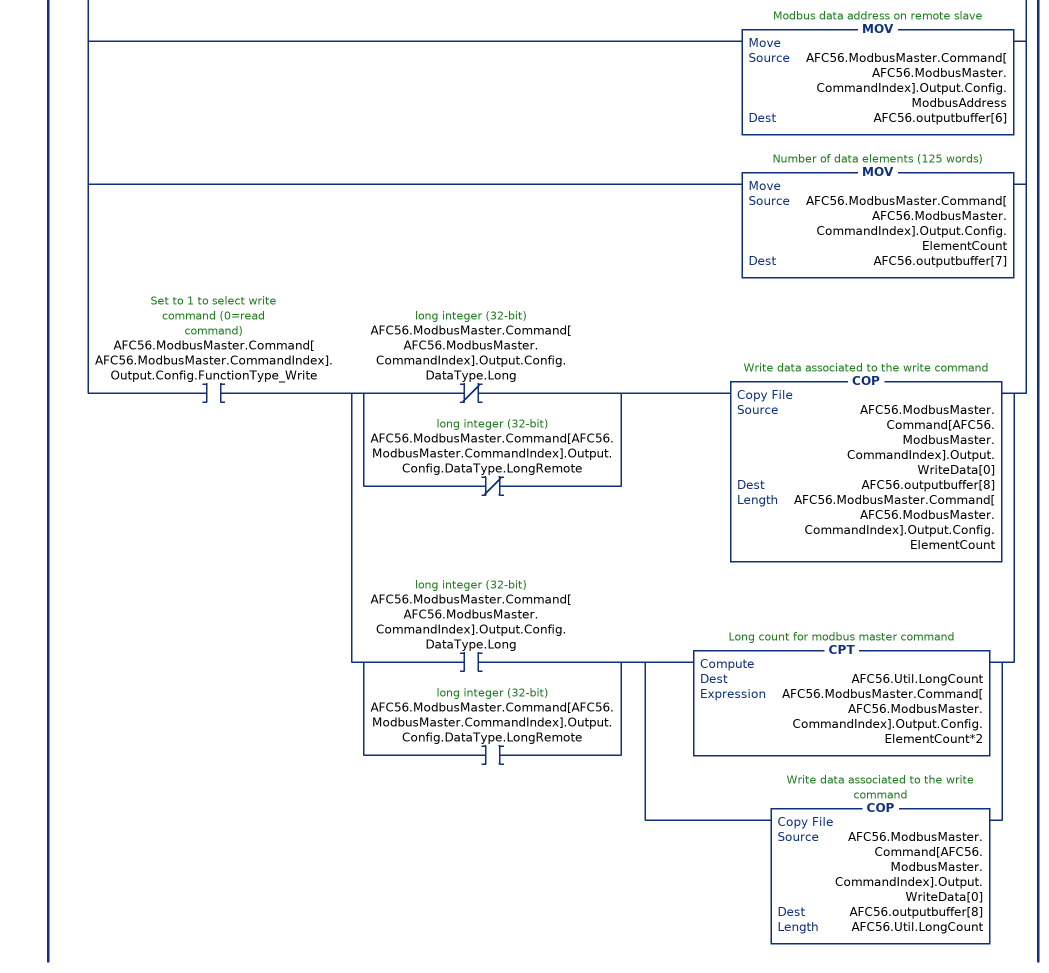
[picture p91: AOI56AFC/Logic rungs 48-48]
   48: XIO(AFC56.Flags.AFC_Set_Clock)[EQU(AFC56.CycleCounter,1000) ,EQU(AFC56.CycleCounter,1001) ]XIC(AFC56.ModbusMaster.Enable)[MOV(131,AFC56.outputbuffer[1]) ,MOV(AFC56.ModbusMaster.Command[AFC56.ModbusMaster.CommandIndex].Output.BOD,AFC56.outputbuffer[2]) ,MOV(AFC56.ModbusMaster.Command[AFC56.ModbusMaster.CommandIndex].Output.TransactionNumber,AFC56.outputbuffer[3]) ,MOV(AFC56.ModbusMaster.Command[AFC56.ModbusMaster.CommandIndex].Output.Config.Type_Swap,AFC56.outputbuffer[4]) ,MOV(AFC56.ModbusMaster.Command[AFC56.ModbusMaster.CommandIndex].Output.Config.SlaveAddress,AFC56.outputbuffer[5]) ,MOV(AFC56.ModbusMaster.Command[AFC56.ModbusMaster.CommandIndex].Output.Config.ModbusAddress,AFC56.outputbuffer[6]) ,MOV(AFC56.ModbusMaster.Command[AFC56.ModbusMaster.CommandIndex].Output.Config.ElementCount,AFC56.outputbuffer[7]) ,XIC(AFC56.ModbusMaster.Command[AFC56.ModbusMaster.CommandIndex].Output.Config.FunctionType_Write) [[XIO(AFC56.ModbusMaster.Command[AFC56.ModbusMaster.CommandIndex].Output.Config.DataType.Long) ,XIO(AFC56.ModbusMaster.Command[AFC56.ModbusMaster.CommandIndex].Output.Config.DataType.LongRemote) ] COP(AFC56.ModbusMaster.Command[AFC56.ModbusMaster.CommandIndex].Output.WriteData[0],AFC56.outputbuffer[8],AFC56.ModbusMaster.Command[AFC56.ModbusMaster.CommandIndex].Output.Config.ElementCount) ,[XIC(AFC56.ModbusMaster.Command[AFC56.ModbusMaster.CommandIndex].Output.Config.DataType.Long) ,XIC(AFC56.ModbusMaster.Command[AFC56.ModbusMaster.CommandIndex].Output.Config.DataType.LongRemote) ] [CPT(AFC56.Util.LongCount,AFC56.ModbusMaster.Command[AFC56.ModbusMaster.CommandIndex].Output.Config.ElementCount*2) ,COP(AFC56.ModbusMaster.Command[AFC56.ModbusMaster.CommandIndex].Output.WriteData[0],AFC56.outputbuffer[8],AFC56.Util.LongCount) ] ] ];
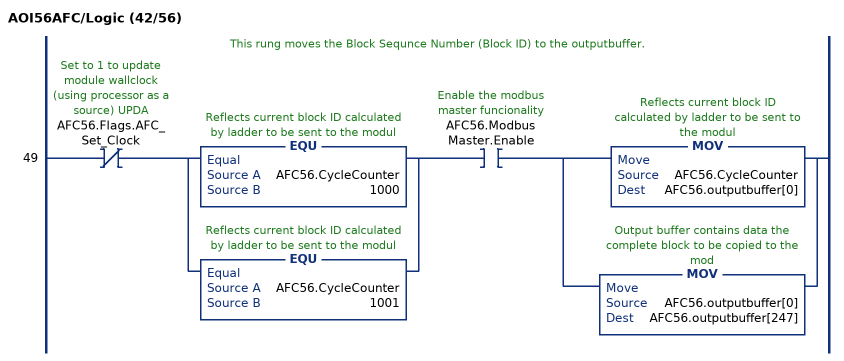
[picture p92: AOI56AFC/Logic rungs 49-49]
   // This rung moves the Block Sequnce Number (Block ID) to the outputbuffer.
   49: XIO(AFC56.Flags.AFC_Set_Clock)[EQU(AFC56.CycleCounter,1000) ,EQU(AFC56.CycleCounter,1001) ]XIC(AFC56.ModbusMaster.Enable)[MOV(AFC56.CycleCounter,AFC56.outputbuffer[0]) ,MOV(AFC56.outputbuffer[0],AFC56.outputbuffer[247]) ];
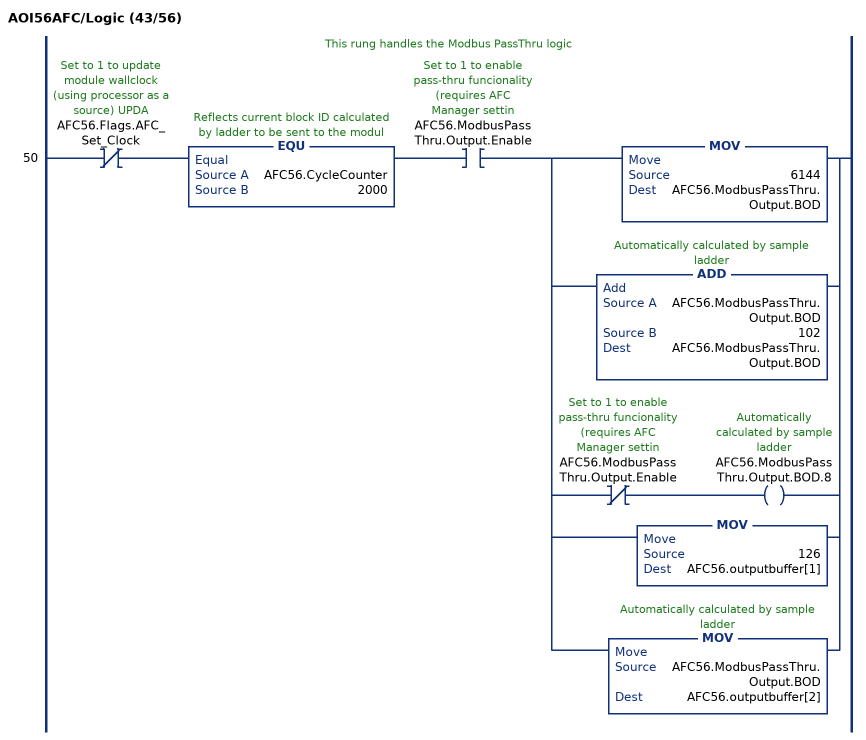
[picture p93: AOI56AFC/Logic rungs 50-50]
   // This rung handles the Modbus PassThru logic
   50: XIO(AFC56.Flags.AFC_Set_Clock)EQU(AFC56.CycleCounter,2000)XIC(AFC56.ModbusPassThru.Output.Enable)[MOV(6144,AFC56.ModbusPassThru.Output.BOD) ,ADD(AFC56.ModbusPassThru.Output.BOD,102,AFC56.ModbusPassThru.Output.BOD) ,XIO(AFC56.ModbusPassThru.Output.Enable) OTE(AFC56.ModbusPassThru.Output.BOD.8) ,MOV(126,AFC56.outputbuffer[1]) ,MOV(AFC56.ModbusPassThru.Output.BOD,AFC56.outputbuffer[2]) ];
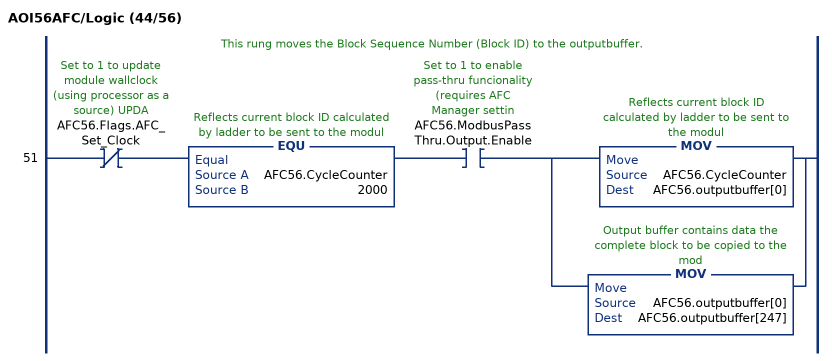
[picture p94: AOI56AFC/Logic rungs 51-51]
   // This rung moves the Block Sequence Number (Block ID) to the outputbuffer.
   51: XIO(AFC56.Flags.AFC_Set_Clock)EQU(AFC56.CycleCounter,2000)XIC(AFC56.ModbusPassThru.Output.Enable)[MOV(AFC56.CycleCounter,AFC56.outputbuffer[0]) ,MOV(AFC56.outputbuffer[0],AFC56.outputbuffer[247]) ];
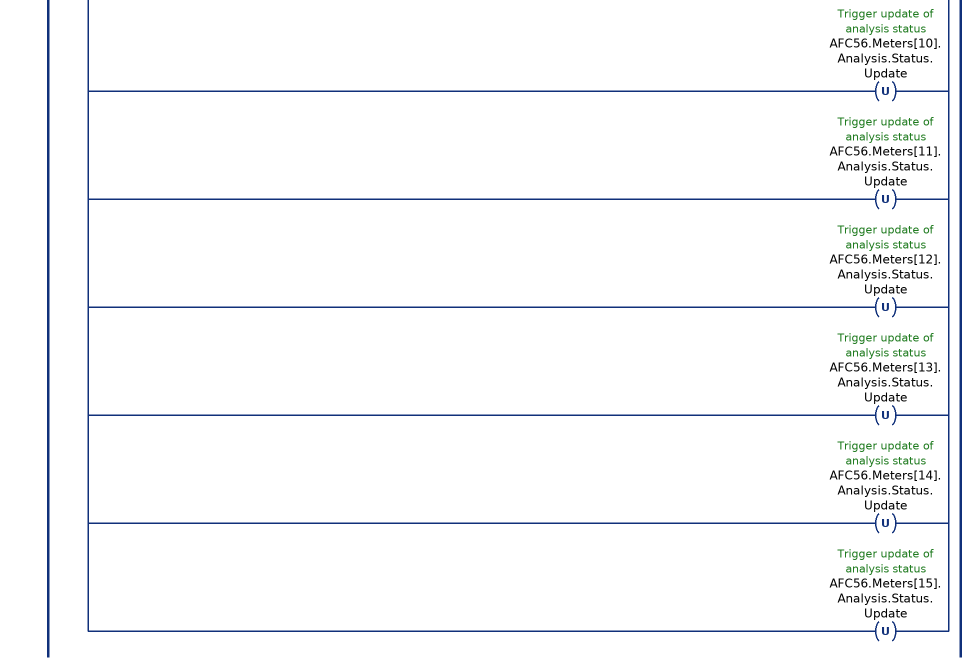
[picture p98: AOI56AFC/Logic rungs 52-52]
   52: XIO(AFC56.Flags.AFC_Set_Clock)XIC(AFC56.inputbuffer[247].11)LIM(3000,AFC56.CycleCounter,3009)EQU(AFC56.CycleCounter,3000)[XIC(AFC56.Meters[0].Analysis.Status.Update) ,XIC(AFC56.Meters[1].Analysis.Status.Update) ,XIC(AFC56.Meters[2].Analysis.Status.Update) ,XIC(AFC56.Meters[3].Analysis.Status.Update) ,XIC(AFC56.Meters[4].Analysis.Status.Update) ,XIC(AFC56.Meters[5].Analysis.Status.Update) ,XIC(AFC56.Meters[6].Analysis.Status.Update) ,XIC(AFC56.Meters[7].Analysis.Status.Update) ,XIC(AFC56.Meters[8].Analysis.Status.Update) ,XIC(AFC56.Meters[9].Analysis.Status.Update) ,XIC(AFC56.Meters[10].Analysis.Status.Update) ,XIC(AFC56.Meters[11].Analysis.Status.Update) ,XIC(AFC56.Meters[12].Analysis.Status.Update) ,XIC(AFC56.Meters[13].Analysis.Status.Update) ,XIC(AFC56.Meters[14].Analysis.Status.Update) ,XIC(AFC56.Meters[15].Analysis.Status.Update) ][MOV(11553,AFC56.Util.AnalysisHighPrecisionBID_Update) ,MOV(49,AFC56.outputbuffer[1]) ,MOV(AFC56.Util.AnalysisHighPrecisionBID_Update,AFC56.outputbuffer[2]) ,OTU(AFC56.Meters[0].Analysis.Status.Update) ,OTU(AFC56.Meters[1].Analysis.Status.Update) ,OTU(AFC56.Meters[2].Analysis.Status.Update) ,OTU(AFC56.Meters[3].Analysis.Status.Update) ,OTU(AFC56.Meters[4].Analysis.Status.Update) ,OTU(AFC56.Meters[5].Analysis.Status.Update) ,OTU(AFC56.Meters[6].Analysis.Status.Update) ,OTU(AFC56.Meters[7].Analysis.Status.Update) ,OTU(AFC56.Meters[8].Analysis.Status.Update) ,OTU(AFC56.Meters[9].Analysis.Status.Update) ,OTU(AFC56.Meters[10].Analysis.Status.Update) ,OTU(AFC56.Meters[11].Analysis.Status.Update) ,OTU(AFC56.Meters[12].Analysis.Status.Update) ,OTU(AFC56.Meters[13].Analysis.Status.Update) ,OTU(AFC56.Meters[14].Analysis.Status.Update) ,OTU(AFC56.Meters[15].Analysis.Status.Update) ];
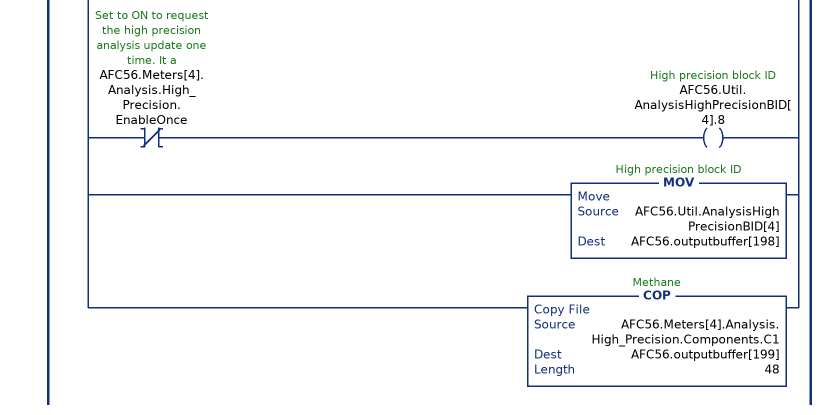
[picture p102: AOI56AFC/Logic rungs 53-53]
   53: XIO(AFC56.Flags.AFC_Set_Clock)XIC(AFC56.inputbuffer[247].11)LIM(3000,AFC56.CycleCounter,3009)EQU(AFC56.CycleCounter,3001)[MOV(245,AFC56.outputbuffer[1]) ,MOV(0,AFC56.Util.Meter_HighAnalysis) ,CPT(AFC56.Util.AnalysisHighPrecisionBID[0],AFC56.Meters[0].Analysis.High_Precision.Stream*32+AFC56.Util.Meter_HighAnalysis+1+11264) ,XIO(AFC56.Meters[0].Analysis.High_Precision.EnableOnce) OTE(AFC56.Util.AnalysisHighPrecisionBID[0].8) ,MOV(AFC56.Util.AnalysisHighPrecisionBID[0],AFC56.outputbuffer[2]) ,COP(AFC56.Meters[0].Analysis.High_Precision.Components.C1,AFC56.outputbuffer[3],48) ,MOV(1,AFC56.Util.Meter_HighAnalysis) ,CPT(AFC56.Util.AnalysisHighPrecisionBID[1],AFC56.Meters[1].Analysis.High_Precision.Stream*32+AFC56.Util.Meter_HighAnalysis+1+11264) ,XIO(AFC56.Meters[1].Analysis.High_Precision.EnableOnce) OTE(AFC56.Util.AnalysisHighPrecisionBID[1].8) ,MOV(AFC56.Util.AnalysisHighPrecisionBID[1],AFC56.outputbuffer[51]) ,COP(AFC56.Meters[1].Analysis.High_Precision.Components.C1,AFC56.outputbuffer[52],48) ,MOV(2,AFC56.Util.Meter_HighAnalysis) ,CPT(AFC56.Util.AnalysisHighPrecisionBID[2],AFC56.Meters[2].Analysis.High_Precision.Stream*32+AFC56.Util.Meter_HighAnalysis+1+11264) ,XIO(AFC56.Meters[2].Analysis.High_Precision.EnableOnce) OTE(AFC56.Util.AnalysisHighPrecisionBID[2].8) ,MOV(AFC56.Util.AnalysisHighPrecisionBID[2],AFC56.outputbuffer[100]) ,COP(AFC56.Meters[2].Analysis.High_Precision.Components.C1,AFC56.outputbuffer[101],48) ,MOV(3,AFC56.Util.Meter_HighAnalysis) ,CPT(AFC56.Util.AnalysisHighPrecisionBID[3],AFC56.Meters[3].Analysis.High_Precision.Stream*32+AFC56.Util.Meter_HighAnalysis+1+11264) ,XIO(AFC56.Meters[3].Analysis.High_Precision.EnableOnce) OTE(AFC56.Util.AnalysisHighPrecisionBID[3].8) ,MOV(AFC56.Util.AnalysisHighPrecisionBID[3],AFC56.outputbuffer[149]) ,COP(AFC56.Meters[3].Analysis.High_Precision.Components.C1,AFC56.outputbuffer[150],48) ,MOV(4,AFC56.Util.Meter_HighAnalysis) ,CPT(AFC56.Util.AnalysisHighPrecisionBID[4],AFC56.Meters[4].Analysis.High_Precision.Stream*32+AFC56.Util.Meter_HighAnalysis+1+11264) ,XIO(AFC56.Meters[4].Analysis.High_Precision.EnableOnce) OTE(AFC56.Util.AnalysisHighPrecisionBID[4].8) ,MOV(AFC56.Util.AnalysisHighPrecisionBID[4],AFC56.outputbuffer[198]) ,COP(AFC56.Meters[4].Analysis.High_Precision.Components.C1,AFC56.outputbuffer[199],48) ];
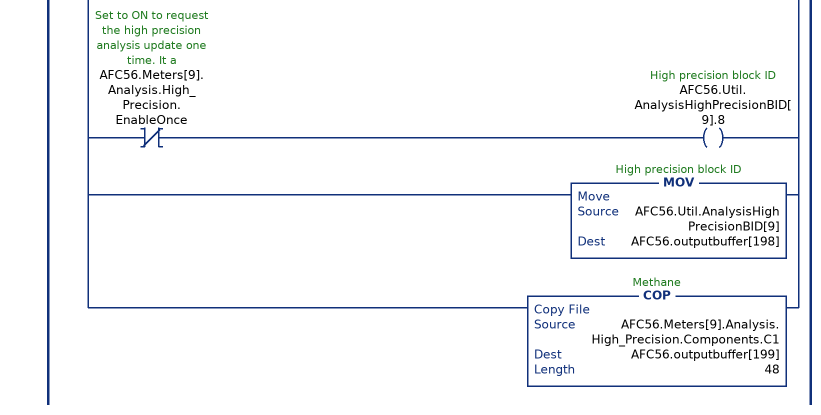
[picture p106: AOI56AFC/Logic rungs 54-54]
   54: XIO(AFC56.Flags.AFC_Set_Clock)XIC(AFC56.inputbuffer[247].11)LIM(3000,AFC56.CycleCounter,3009)EQU(AFC56.CycleCounter,3002)[MOV(245,AFC56.outputbuffer[1]) ,MOV(5,AFC56.Util.Meter_HighAnalysis) ,CPT(AFC56.Util.AnalysisHighPrecisionBID[5],AFC56.Meters[5].Analysis.High_Precision.Stream*32+AFC56.Util.Meter_HighAnalysis+1+11264) ,XIO(AFC56.Meters[5].Analysis.High_Precision.EnableOnce) OTE(AFC56.Util.AnalysisHighPrecisionBID[5].8) ,MOV(AFC56.Util.AnalysisHighPrecisionBID[5],AFC56.outputbuffer[2]) ,COP(AFC56.Meters[5].Analysis.High_Precision.Components.C1,AFC56.outputbuffer[3],48) ,MOV(6,AFC56.Util.Meter_HighAnalysis) ,CPT(AFC56.Util.AnalysisHighPrecisionBID[6],AFC56.Meters[6].Analysis.High_Precision.Stream*32+AFC56.Util.Meter_HighAnalysis+1+11264) ,XIO(AFC56.Meters[6].Analysis.High_Precision.EnableOnce) OTE(AFC56.Util.AnalysisHighPrecisionBID[6].8) ,MOV(AFC56.Util.AnalysisHighPrecisionBID[6],AFC56.outputbuffer[51]) ,COP(AFC56.Meters[6].Analysis.High_Precision.Components.C1,AFC56.outputbuffer[52],48) ,MOV(7,AFC56.Util.Meter_HighAnalysis) ,CPT(AFC56.Util.AnalysisHighPrecisionBID[7],AFC56.Meters[7].Analysis.High_Precision.Stream*32+AFC56.Util.Meter_HighAnalysis+1+11264) ,XIO(AFC56.Meters[7].Analysis.High_Precision.EnableOnce) OTE(AFC56.Util.AnalysisHighPrecisionBID[7].8) ,MOV(AFC56.Util.AnalysisHighPrecisionBID[7],AFC56.outputbuffer[100]) ,COP(AFC56.Meters[7].Analysis.High_Precision.Components.C1,AFC56.outputbuffer[101],48) ,MOV(8,AFC56.Util.Meter_HighAnalysis) ,CPT(AFC56.Util.AnalysisHighPrecisionBID[8],AFC56.Meters[8].Analysis.High_Precision.Stream*32+AFC56.Util.Meter_HighAnalysis+1+11264) ,XIO(AFC56.Meters[8].Analysis.High_Precision.EnableOnce) OTE(AFC56.Util.AnalysisHighPrecisionBID[8].8) ,MOV(AFC56.Util.AnalysisHighPrecisionBID[8],AFC56.outputbuffer[149]) ,COP(AFC56.Meters[8].Analysis.High_Precision.Components.C1,AFC56.outputbuffer[150],48) ,MOV(9,AFC56.Util.Meter_HighAnalysis) ,CPT(AFC56.Util.AnalysisHighPrecisionBID[9],AFC56.Meters[9].Analysis.High_Precision.Stream*32+AFC56.Util.Meter_HighAnalysis+1+11264) ,XIO(AFC56.Meters[9].Analysis.High_Precision.EnableOnce) OTE(AFC56.Util.AnalysisHighPrecisionBID[9].8) ,MOV(AFC56.Util.AnalysisHighPrecisionBID[9],AFC56.outputbuffer[198]) ,COP(AFC56.Meters[9].Analysis.High_Precision.Components.C1,AFC56.outputbuffer[199],48) ];
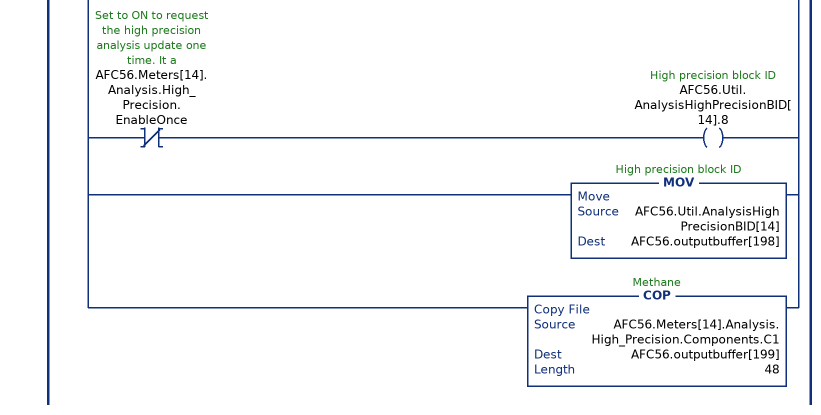
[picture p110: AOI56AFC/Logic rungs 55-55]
   55: XIO(AFC56.Flags.AFC_Set_Clock)XIC(AFC56.inputbuffer[247].11)LIM(3000,AFC56.CycleCounter,3009)EQU(AFC56.CycleCounter,3003)[MOV(245,AFC56.outputbuffer[1]) ,MOV(10,AFC56.Util.Meter_HighAnalysis) ,CPT(AFC56.Util.AnalysisHighPrecisionBID[10],AFC56.Meters[10].Analysis.High_Precision.Stream*32+AFC56.Util.Meter_HighAnalysis+1+11264) ,XIO(AFC56.Meters[10].Analysis.High_Precision.EnableOnce) OTE(AFC56.Util.AnalysisHighPrecisionBID[10].8) ,MOV(AFC56.Util.AnalysisHighPrecisionBID[10],AFC56.outputbuffer[2]) ,COP(AFC56.Meters[10].Analysis.High_Precision.Components.C1,AFC56.outputbuffer[3],48) ,MOV(11,AFC56.Util.Meter_HighAnalysis) ,CPT(AFC56.Util.AnalysisHighPrecisionBID[11],AFC56.Meters[11].Analysis.High_Precision.Stream*32+AFC56.Util.Meter_HighAnalysis+1+11264) ,XIO(AFC56.Meters[11].Analysis.High_Precision.EnableOnce) OTE(AFC56.Util.AnalysisHighPrecisionBID[11].8) ,MOV(AFC56.Util.AnalysisHighPrecisionBID[11],AFC56.outputbuffer[51]) ,COP(AFC56.Meters[11].Analysis.High_Precision.Components.C1,AFC56.outputbuffer[52],48) ,MOV(12,AFC56.Util.Meter_HighAnalysis) ,CPT(AFC56.Util.AnalysisHighPrecisionBID[12],AFC56.Meters[12].Analysis.High_Precision.Stream*32+AFC56.Util.Meter_HighAnalysis+1+11264) ,XIO(AFC56.Meters[12].Analysis.High_Precision.EnableOnce) OTE(AFC56.Util.AnalysisHighPrecisionBID[12].8) ,MOV(AFC56.Util.AnalysisHighPrecisionBID[12],AFC56.outputbuffer[100]) ,COP(AFC56.Meters[12].Analysis.High_Precision.Components.C1,AFC56.outputbuffer[101],48) ,MOV(13,AFC56.Util.Meter_HighAnalysis) ,CPT(AFC56.Util.AnalysisHighPrecisionBID[13],AFC56.Meters[13].Analysis.High_Precision.Stream*32+AFC56.Util.Meter_HighAnalysis+1+11264) ,XIO(AFC56.Meters[13].Analysis.High_Precision.EnableOnce) OTE(AFC56.Util.AnalysisHighPrecisionBID[13].8) ,MOV(AFC56.Util.AnalysisHighPrecisionBID[13],AFC56.outputbuffer[149]) ,COP(AFC56.Meters[13].Analysis.High_Precision.Components.C1,AFC56.outputbuffer[150],48) ,MOV(14,AFC56.Util.Meter_HighAnalysis) ,CPT(AFC56.Util.AnalysisHighPrecisionBID[14],AFC56.Meters[14].Analysis.High_Precision.Stream*32+AFC56.Util.Meter_HighAnalysis+1+11264) ,XIO(AFC56.Meters[14].Analysis.High_Precision.EnableOnce) OTE(AFC56.Util.AnalysisHighPrecisionBID[14].8) ,MOV(AFC56.Util.AnalysisHighPrecisionBID[14],AFC56.outputbuffer[198]) ,COP(AFC56.Meters[14].Analysis.High_Precision.Components.C1,AFC56.outputbuffer[199],48) ];
